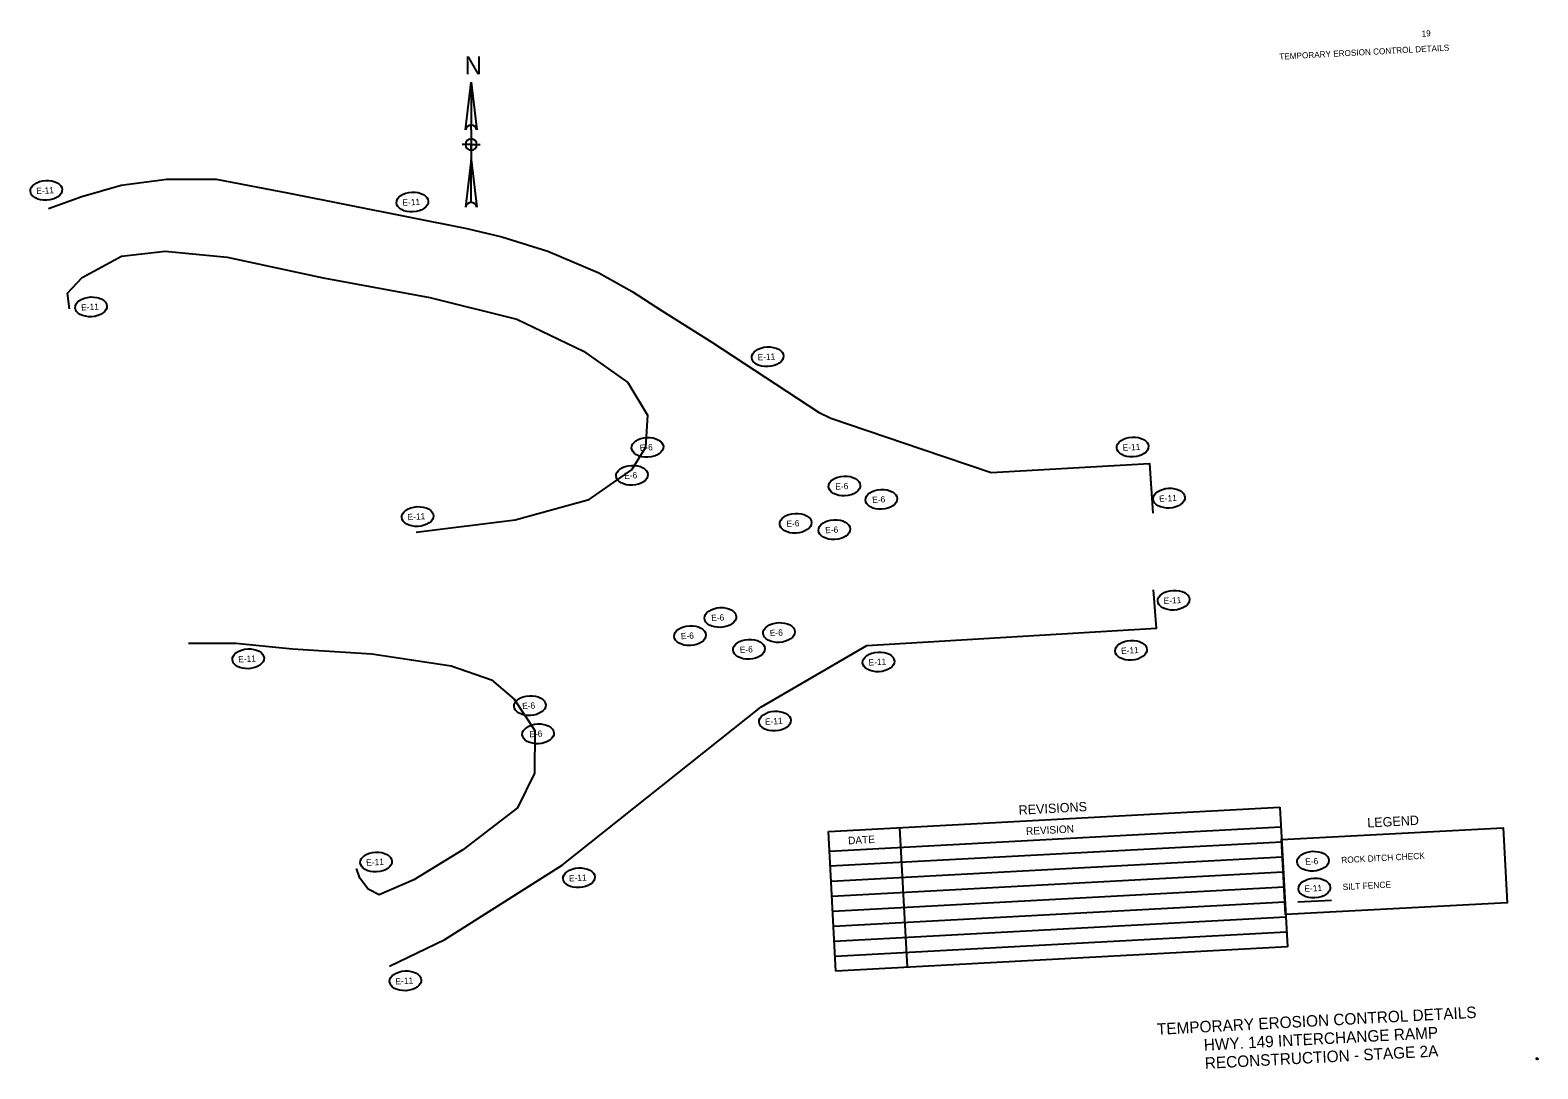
# Model space of a CAD drawing. Extents: x 251493 to 254667, y 216764 to 225410.
# Drawn here: x 251659 to 254548, y 218982 to 220973 of the extents above; entities that cross this region are included whole.
import ezdxf

# ---------------------------------------------------------------- set-up
doc = ezdxf.new("R2010")
doc.units = 0
for name, color, linetype in [('24X36', 7, 'Continuous'), ('Level 1', 7, 'Continuous'), ('Level 2', 7, 'Continuous'), ('Level 30', 7, 'Continuous')]:
    doc.layers.add(name, color=color, linetype=linetype)

msp = doc.modelspace()

# ---------------------------------------------------------------- linework, layer by layer
at = {"layer": '24X36'}
msp.add_line((254088.5, 219302.2), (254152.4, 219305.6), dxfattribs=at)
for points in [[(251694.2, 220631.2), (251758.1, 220654.4), (251833.5, 220676.1), (251921.1, 220687.6), (252015.6, 220687.3), (252155.5, 220660.7), (252495.8, 220592.8), (252563.3, 220576.7), (252650.9, 220549.7), (252749.1, 220508.3), (252812.6, 220472), (252869, 220435.8), (252965.2, 220375.2), (253170.1, 220240.9), (253193.4, 220229.5), (253368.2, 220170.1), (253500.4, 220125.2), (253804.2, 220142.4), (253810.4, 220047.6)], [(251734.7, 220439.1), (251730.7, 220468.8), (251759, 220499), (251834.5, 220540.1), (251917.7, 220549.4), (252036.8, 220537.8), (252220.7, 220498.6), (252424.8, 220460.5), (252592.1, 220419.3), (252719.8, 220357.9), (252804.3, 220297.9), (252842.4, 220235.3), (252838.5, 220172.9), (252812.1, 220130.8), (252727.9, 220072.5), (252588.8, 220034), (252398.7, 220010.6)], [(252348, 219179), (252454.1, 219230.1), (252678.5, 219372.5), (253059, 219675.2), (253262.5, 219793.4), (253817.2, 219826.7), (253811.4, 219900.6)], [(251962.8, 219798.3), (252053.7, 219798.4), (252161.9, 219787.4), (252314.3, 219777.7), (252466.2, 219754.7), (252543, 219727.7), (252586.9, 219690.6), (252626, 219630.5), (252625.6, 219549.1), (252593.2, 219482.8), (252488.1, 219401.9), (252394.3, 219344.8), (252328.3, 219315.5), (252306.8, 219326.9), (252291.3, 219347.6), (252284.3, 219366.4)]]:
    msp.add_lwpolyline(points, dxfattribs=at)
for centre in [(251776, 220442.8), (252842.1, 220173.5), (252812.3, 220119.9), (253219.5, 220099.4), (253290.2, 220073.8), (252401.6, 220040.9), (253125.9, 220028), (253200.1, 220015.8), (252981.8, 219847.4), (253094, 219818.6), (252923.6, 219812.6), (253036.5, 219786.4), (252077.1, 219768.2), (252616.8, 219678.5), (252632.6, 219624.4), (252322.2, 219378.7)]:
    msp.add_ellipse(centre, major_axis=(30.4, 1.6), ratio=0.622507, dxfattribs=at)
at = {"layer": 'Level 1'}
for p, q in [((252493.5, 220782.1), (252504.4, 220873.5)), ((252504.4, 220873.5), (252515.2, 220782.1)), ((252504.4, 220873.5), (252504.4, 220790.8)), ((252504.4, 220782.1), (252504.4, 220790.8)), ((252504.4, 220782.1), (252504.4, 220764.6)), ((252504.4, 220764.6), (252504.4, 220753.7)), ((252493, 220753.7), (252486.9, 220753.7)), ((252504.4, 220753.7), (252493.8, 220753.7)), ((252504.4, 220753.7), (252504.4, 220742.9)), ((252504.4, 220753.7), (252515.2, 220753.7)), ((252504.4, 220742.9), (252504.4, 220753.7)), ((252504.4, 220742.9), (252504.4, 220725.5)), ((252515.2, 220753.7), (252521.8, 220753.7)), ((252515.2, 220753.7), (252515.2, 220753.7)), ((252504.4, 220725.5), (252493.5, 220634)), ((252504.4, 220642.7), (252504.4, 220725.5)), ((252504.4, 220725.5), (252515.2, 220634)), ((253188.8, 219437.2), (254053.8, 219483.6)), ((254053.8, 219483.6), (254068.1, 219216.1)), ((253203.1, 219169.8), (253188.8, 219437.2)), ((253190.8, 219399.8), (254055.8, 219446.2)), ((253325.2, 219444.5), (253339.5, 219177.1)), ((253192.3, 219371.1), (254057.4, 219417.4)), ((253193.9, 219342.3), (254058.9, 219388.6)), ((253195.4, 219313.5), (254060.4, 219359.9)), ((253197, 219284.8), (254062, 219331.1)), ((253198.5, 219256), (254063.5, 219302.4)), ((253200, 219227.3), (254065.1, 219273.6)), ((253201.6, 219198.5), (254066.6, 219244.9)), ((254068.1, 219216.1), (253203.1, 219169.8)), ((254068.1, 219216.1), (254068.1, 219216.1))]:
    msp.add_line(p, q, dxfattribs=at)
msp.add_lwpolyline([(254057.1, 219421.7), (254481.3, 219444.5), (254489, 219300.7), (254064.8, 219277.9)], close=True, dxfattribs=at)
for points in [[(254546.1, 219002.3), (254544.7, 219002.2), (254544.7, 219002.1), (254545.3, 219002.1), (254545.4, 219000.6), (254545.6, 219000.6), (254545.5, 219002.1), (254546.1, 219002.1), (254546.1, 219002.3)], [(254546.1, 219002.3), (254544.7, 219002.2), (254544.7, 219002.1), (254545.3, 219002.1), (254545.4, 219000.6), (254545.6, 219000.6), (254545.5, 219002.1), (254546.1, 219002.1), (254546.1, 219002.3)], [(254546.5, 219002.1), (254546.5, 219002.1), (254547.1, 219000.7), (254547.3, 219000.7), (254547.8, 219002.1), (254547.8, 219002.1), (254547.8, 219000.7), (254548.1, 219000.7), (254548, 219002.4), (254547.7, 219002.4), (254547.2, 219000.9), (254546.6, 219002.3), (254546.3, 219002.3), (254546.4, 219000.6), (254546.6, 219000.6), (254546.5, 219002.1)], [(254546.5, 219002.1), (254546.5, 219002.1), (254547.1, 219000.7), (254547.3, 219000.7), (254547.8, 219002.1), (254547.8, 219002.1), (254547.8, 219000.7), (254548.1, 219000.7), (254548, 219002.4), (254547.7, 219002.4), (254547.2, 219000.9), (254546.6, 219002.3), (254546.3, 219002.3), (254546.4, 219000.6), (254546.6, 219000.6), (254546.5, 219002.1)]]:
    msp.add_lwpolyline(points, dxfattribs=at)
for centre, radius, start, end in [((252504.4, 220779.6), 11.2, 90, 167.3196), ((252504.4, 220779.6), 11.2, 12.6804, 90), ((252504.4, 220753.8), 10.9, 90, 180), ((252504.4, 220753.8), 10.9, 0, 90), ((252504.4, 220753.8), 10.9, 180, 270), ((252504.4, 220753.8), 10.9, 270, 0), ((252504.4, 220631.6), 11.2, 90, 167.3196), ((252504.4, 220631.6), 11.2, 12.6804, 90)]:
    msp.add_arc(centre, radius, start, end, dxfattribs=at)
at = {"layer": 'Level 30'}
for centre in [(251690.2, 220666), (252391.7, 220643.7), (253072.3, 220347.1), (253771.7, 220174.1), (253841.5, 220076.1), (253850.2, 219880.5), (253768.6, 219784.6), (253284.8, 219762.3), (253086.4, 219648.8), (254117.1, 219380.3), (252710.8, 219348.5), (254119.9, 219328.8), (252378.4, 219151)]:
    msp.add_ellipse(centre, major_axis=(30.4, 1.6), ratio=0.622507, dxfattribs=at)

# ---------------------------------------------------------------- texts
at = {"layer": '24X36'}
for s, p in [('E-11', (251757.3, 220435.6)), ('E-6', (252827.6, 220166.6)), ('E-6', (252797.8, 220113)), ('E-6', (253202.3, 220092.3)), ('E-6', (253273, 220066.8)), ('E-11', (252382.8, 220033.8)), ('E-6', (253108.7, 220020.9)), ('E-6', (253182.9, 220008.7)), ('E-6', (252964.6, 219840.4)), ('E-6', (252906.4, 219805.6)), ('E-6', (253076.8, 219811.5)), ('E-6', (253019.3, 219779.3)), ('E-11', (252058.3, 219761.1)), ('E-6', (252602.3, 219671.6)), ('E-6', (252616, 219617.7)), ('E-11', (252303.4, 219371.5))]:
    msp.add_text(s, height=12, rotation=3.0666, dxfattribs=at).set_placement(p)
at = {"layer": 'Level 1'}
for s, height, p in [('19', 11.72, (254325.7, 220960.5)), ('TEMPORARY EROSION CONTROL DETAILS', 11.7, (254053, 220916.5)), ('DATE', 14.4, (253226.9, 219412.5)), ('REVISION', 14.4, (253567.7, 219430.5))]:
    msp.add_text(s, height=height, rotation=3.0666, dxfattribs=at).set_placement(p)
msp.add_text('N', height=34.2, dxfattribs=at).set_placement((252491.7, 220888.6))
at = {"layer": 'Level 2'}
for s, p in [('TEMPORARY EROSION CONTROL DETAILS', (253818.9, 219047.3)), ('HWY. 149 INTERCHANGE RAMP', (253908.6, 219017.1)), ('RECONSTRUCTION - STAGE 2A', (253910.6, 218982.1))]:
    msp.add_text(s, height=22, rotation=3.0666, dxfattribs=at).set_placement(p)
at = {"layer": 'Level 30'}
for s, height, p in [('E-11', 12, (251671.4, 220658.8)), ('E-11', 12, (252372.9, 220636.6)), ('E-11', 12, (253053.5, 220340)), ('E-11', 12, (253752.9, 220166.9)), ('E-11', 12, (253822.7, 220069)), ('E-11', 12, (253831.4, 219873.3)), ('E-11', 12, (253749.8, 219777.5)), ('E-11', 12, (253266, 219755.1)), ('E-11', 12, (253067.6, 219641.6)), ('REVISIONS', 18, (253553.7, 219469.2)), ('LEGEND', 18, (254221.7, 219444.8)), ('E-6', 12, (254102.6, 219373.4)), ('ROCK DITCH CHECK', 11.997, (254171.6, 219376.4)), ('E-11', 12, (252692, 219341.3)), ('SILT FENCE ', 11.997, (254174.4, 219324.9)), ('E-11', 12, (254101.1, 219321.6)), ('E-11', 12, (252359.6, 219143.8))]:
    msp.add_text(s, height=height, rotation=3.0666, dxfattribs=at).set_placement(p)

doc.saveas('drawing.dxf')
